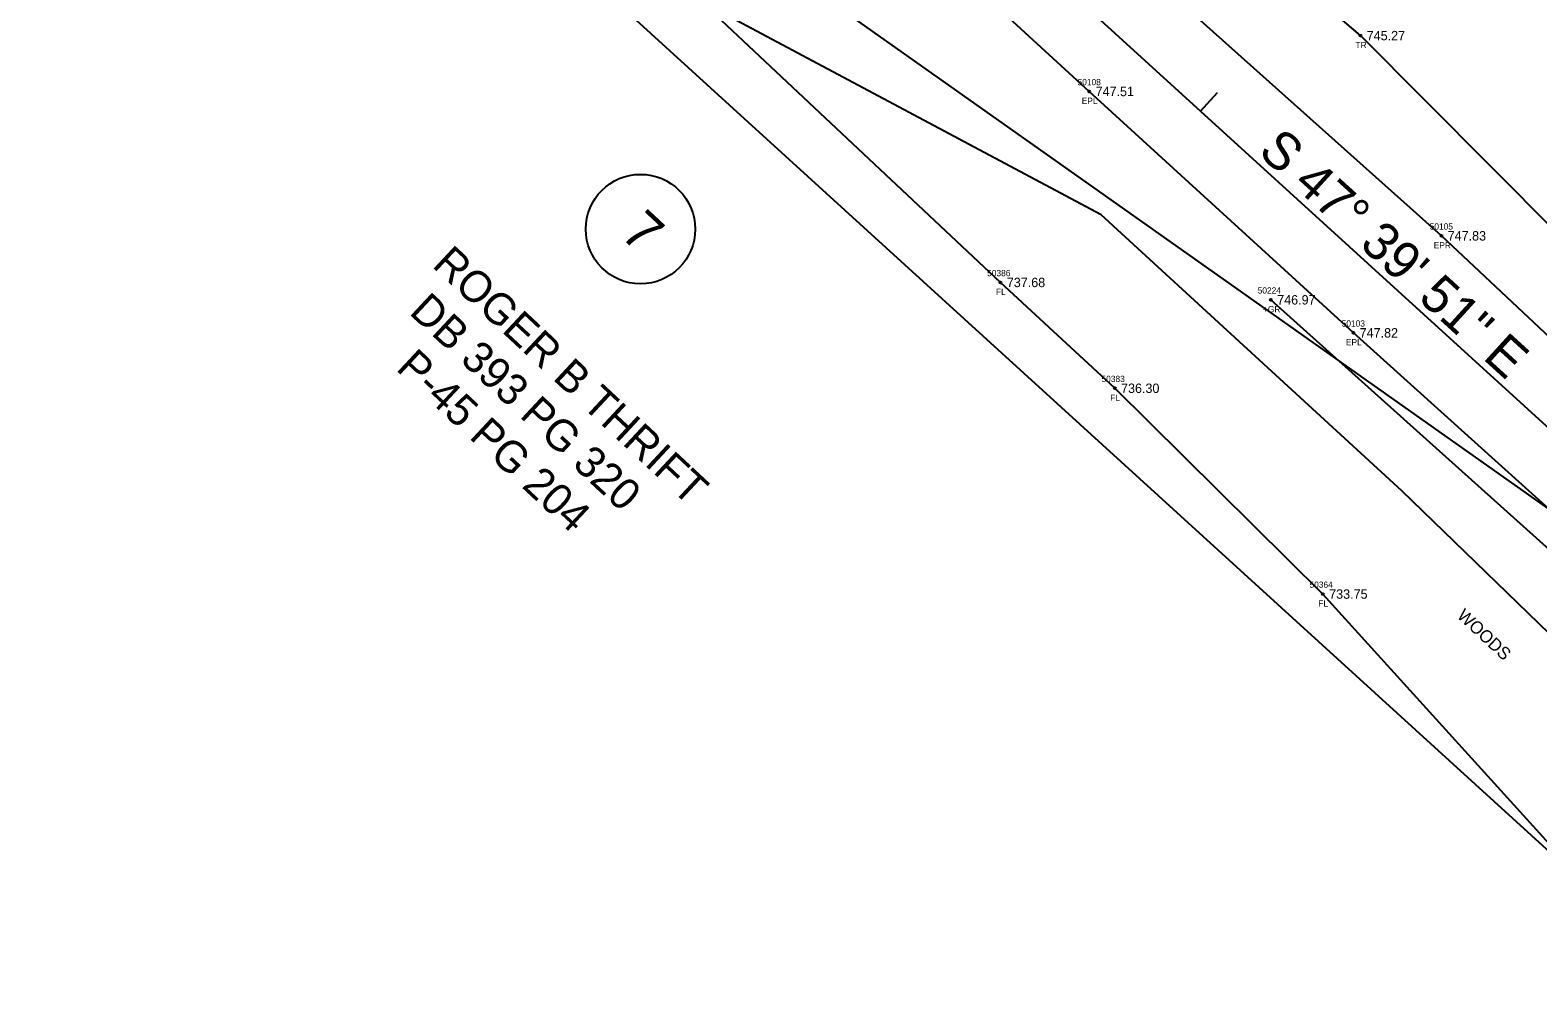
# Model space of a CAD drawing. Extents: x 1378245 to 1381654, y 996521 to 1000567.
# Drawn here: x 1379299.2 to 1379540.2, y 998998.6 to 999152.7 of the extents above; entities that cross this region are included whole.
import ezdxf

# ---------------------------------------------------------------- set-up
doc = ezdxf.new("R2010")
doc.units = 0
for name, color, linetype in [('RD_EX_DV_TX_Prop(Owner ID)', 7, 'Continuous'), ('RD_EX_Fence_Other', 7, 'Continuous'), ('RD_EX_Fence_Other_txCode', 7, 'Continuous'), ('RD_EX_GuardRail', 7, 'Continuous'), ('RD_EX_GuardRail_txCode', 7, 'Continuous'), ('RD_EX_Road', 7, 'Continuous'), ('RD_EX_Road_txCode', 7, 'Continuous'), ('RD_EX_RW', 7, 'Continuous'), ('RD_EX_SU_Elec', 7, 'Continuous'), ('RD_EX_TX_Fence_Other_ELEV', 7, 'Continuous'), ('RD_EX_TX_GuardRail_ELEV', 7, 'Continuous'), ('RD_EX_TX_Road_ELEV', 7, 'Continuous'), ('RD_EX_TX_VEG_ELEV', 7, 'Continuous'), ('RD_EX_VEG', 7, 'Continuous'), ('RD_EX_VEG_txCode', 7, 'Continuous'), ('RD_HC_Cl', 7, 'Continuous'), ('RD_HC_Data', 7, 'Continuous'), ('RD_HC_Data_Tic', 7, 'Continuous'), ('RD_SMD_Locator', 7, 'Continuous'), ('RD_TX_Misc2', 7, 'Continuous')]:
    doc.layers.add(name, color=color, linetype=linetype)

msp = doc.modelspace()

# ---------------------------------------------------------------- linework, layer by layer
at = {"layer": 'RD_EX_DV_TX_Prop(Owner ID)'}
msp.add_circle((1379396.75, 999120.89), 8.75, dxfattribs=at)
at = {"layer": 'RD_EX_Fence_Other'}
msp.add_lwpolyline([(1379613.24, 998940.87), (1379574.4, 998986.01), (1379543.59, 999020.83), (1379505.83, 999062.54), (1379472.56, 999095.44), (1379454.3, 999112.36), (1379373.85, 999187.96), (1379325.25, 999231.37), (1379289.51, 999266.01), (1379255.48, 999295.15), (1379213.9, 999334), (1379169.28, 999374.93), (1379148.65, 999391.69), (1379140.06, 999386.4)], dxfattribs=at)
at = {"layer": 'RD_EX_GuardRail'}
msp.add_lwpolyline([(1379497.52, 999109.58), (1379635.64, 998985.68), (1379713.53, 998914.45), (1379759.99, 998873.32)], dxfattribs=at)
at = {"layer": 'RD_EX_Road'}
for points in [[(1379637.07, 998987.22), (1379597.14, 999025.68), (1379553.31, 999065.91), (1379510.7, 999104.3), (1379468.49, 999142.89), (1379424.88, 999182.89), (1379377.9, 999224.84), (1379333.61, 999264.98), (1379287.28, 999307.21), (1379240.78, 999348.98)], [(1379652.22, 999003.54), (1379610.67, 999040.91), (1379567.41, 999079.79), (1379524.77, 999119.81), (1379481.79, 999158.31), (1379438.69, 999197.69), (1379392.81, 999238.63), (1379346.75, 999280.78), (1379301.8, 999321.66)]]:
    msp.add_lwpolyline(points, dxfattribs=at)
at = {"layer": 'RD_EX_RW'}
msp.add_line((1379378.68, 999170.13), (1379748.28, 998833.39), dxfattribs=at)
at = {"layer": 'RD_EX_SU_Elec'}
msp.add_lwpolyline([(1378514.25, 999944.12), (1378777.7, 999831.22), (1379190.17, 999461.05), (1379403.33, 999174.04), (1379756.94, 998924.25), (1380051.16, 998659.97), (1380327.91, 998390.65), (1380546.23, 998058.37)], dxfattribs=at)
at = {"layer": 'RD_EX_VEG'}
for points in [[(1379635.72, 999031.86), (1379598.35, 999066.81), (1379553.67, 999109.8), (1379511.83, 999151.82), (1379464.53, 999192.2), (1379415.99, 999234.77), (1379368.04, 999279.07), (1379324.89, 999312.56), (1379291.58, 999344.45), (1379199.89, 999450.8), (1379227.01, 999457.75)], [(1379621.71, 998986.05), (1379558.91, 999039.89), (1379518.45, 999079.04), (1379470.36, 999123.18), (1379409.67, 999155.52), (1379381.73, 999202.94), (1379345.95, 999233.83), (1379296.88, 999282.18), (1379264.05, 999313.51), (1379229.78, 999344.81), (1379187.41, 999381.54), (1379155.41, 999406.5), (1379144.25, 999379.18), (1379133.7, 999360.09), (1379119.62, 999335.97)]]:
    msp.add_lwpolyline(points, dxfattribs=at)
at = {"layer": 'RD_HC_Cl'}
msp.add_line((1378781.54, 999781.8), (1380217.09, 998473.92), dxfattribs=at)
at = {"layer": 'RD_HC_Data_Tic'}
msp.add_line((1379486.27, 999139.74), (1379488.97, 999142.7), dxfattribs=at)
at = {"layer": 'RD_SMD_Locator'}
for centre in [(1379511.83, 999151.82), (1379468.49, 999142.89), (1379524.77, 999119.81), (1379454.3, 999112.36), (1379497.52, 999109.58), (1379510.7, 999104.3), (1379472.56, 999095.44), (1379505.83, 999062.54)]:
    msp.add_circle(centre, 0.15, dxfattribs=at)

# ---------------------------------------------------------------- texts
at = {"layer": 'RD_EX_DV_TX_Prop(Owner ID)'}
for s, height, p in [('7', 6.25, (1379393.33, 999119.81)), ('ROGER B THRIFT', 5, (1379363.27, 999114.95)), ('DB 393 PG 320', 5, (1379359.6, 999107.43)), ('P-45 PG 204', 5, (1379357.51, 999098.45))]:
    msp.add_text(s, height=height, rotation=317.0049, dxfattribs=at).set_placement(p)
at = {"layer": 'RD_EX_Fence_Other_txCode'}
for s, p in [('50386', (1379452.16, 999113.36)), ('FL', (1379453.57, 999110.36)), ('50383', (1379470.44, 999096.44)), ('FL', (1379471.83, 999093.44)), ('50364', (1379503.69, 999063.54)), ('FL', (1379505.1, 999060.54))]:
    msp.add_text(s, height=1, dxfattribs=at).set_placement(p)
at = {"layer": 'RD_EX_GuardRail_txCode'}
for s, p in [('50224', (1379495.4, 999110.58)), ('+GR', (1379496.25, 999107.58))]:
    msp.add_text(s, height=1, dxfattribs=at).set_placement(p)
at = {"layer": 'RD_EX_Road_txCode'}
for s, p in [('50108', (1379466.61, 999143.89)), ('EPL', (1379467.28, 999140.89)), ('50105', (1379522.9, 999120.81)), ('EPR', (1379523.55, 999117.81)), ('50103', (1379508.83, 999105.3)), ('EPL', (1379509.5, 999102.3))]:
    msp.add_text(s, height=1, dxfattribs=at).set_placement(p)
at = {"layer": 'RD_EX_TX_Fence_Other_ELEV'}
for s, p in [('737.68', (1379455.3, 999111.61)), ('736.30', (1379473.56, 999094.69)), ('733.75', (1379506.83, 999061.79))]:
    msp.add_text(s, height=1.5, dxfattribs=at).set_placement(p)
at = {"layer": 'RD_EX_TX_GuardRail_ELEV'}
msp.add_text('746.97', height=1.5, dxfattribs=at).set_placement((1379498.52, 999108.83))
at = {"layer": 'RD_EX_TX_Road_ELEV'}
for s, p in [('747.51', (1379469.49, 999142.14)), ('747.83', (1379525.77, 999119.06)), ('747.82', (1379511.7, 999103.55))]:
    msp.add_text(s, height=1.5, dxfattribs=at).set_placement(p)
at = {"layer": 'RD_EX_TX_VEG_ELEV'}
msp.add_text('745.27', height=1.5, dxfattribs=at).set_placement((1379512.83, 999151.07))
at = {"layer": 'RD_EX_VEG_txCode'}
msp.add_text('TR', height=1, dxfattribs=at).set_placement((1379511.04, 999149.82))
at = {"layer": 'RD_HC_Data'}
msp.add_text('S 47%%d 39\' 51" E', height=6, rotation=317.6642, dxfattribs=at).set_placement((1379495.28, 999132.99))
at = {"layer": 'RD_TX_Misc2'}
msp.add_text('WOODS', height=2, rotation=317.0014, dxfattribs=at).set_placement((1379527.14, 999058.89))

doc.saveas('drawing.dxf')
